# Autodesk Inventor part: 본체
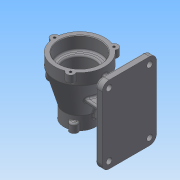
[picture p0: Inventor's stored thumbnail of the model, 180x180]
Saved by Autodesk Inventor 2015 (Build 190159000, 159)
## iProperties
Created: 2020-03
Part Number: 본체
Material: 일반
Document SubType Name: Modeling
Designer: user
Density: 1 g/cm^3
Appearance: 기본값
Author: user
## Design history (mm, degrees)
sketch "스케치1"
  geometry: L1 (0, 0)-(0, 100); L2 (0, 100)-(44, 100); L3 (0, 0)-(27.5, 0); L4 (27.5, 0)-(27.5, 23); L5 (44, 100)-(44, 80); L6 (44, 80)-(27.5, 23)
  constraints: 12 end point, 2 horizontal, 2 vertical, 1 perpendicular
  dimensions: "d0" = 100 distance of L1.start L1.end; "d1" = 44 distance of L1.end L2.end; "d3" = 27.5 distance of L1.start L3.end; "d4" = 23 distance of L3.end L4.end; "d5" = 20 distance of L2.end L5.end
revolve "회전1" sketch "스케치1" stored, may be unused: angle "d6" = 90 deg
hole "구멍1" diameter "d9" = 72; stored, may be unused: countersink angle "d13" = 90 deg, drill point angle "d15" = 0 deg; dims "d7" = 10, "d8" = 10, "d10" = 6, "d11" = 4, "d12" = 2, "d14" = 23
hole "구멍2" diameter "d18" = 52; stored, may be unused: countersink angle "d22" = 90 deg, drill point angle "d24" = 0 deg; dims "d16" = 10, "d17" = 10, "d19" = 6, "d20" = 4, "d21" = 2, "d23" = 47
hole "구멍3" diameter "d27" = 40; stored, may be unused: countersink angle "d31" = 90 deg, drill point angle "d33" = 0 deg; dims "d25" = 10, "d26" = 10, "d28" = 6, "d29" = 4, "d30" = 2, "d32" = 30
chamfer "모따기1" distance "d34" = 1; stored, may be unused: second distance "d35" = 2, angle "d36" = 45 deg
chamfer "모따기2" distance "d37" = 1; stored, may be unused: second distance "d38" = 2, angle "d39" = 45 deg
fillet "모깎기1" dims "d40" = 3
node "작업 평면1"
sketch "스케치2"
  geometry: L1 (-47.5, -16)-(-47.5, 119); L2 (47.5, -16)-(47.5, 119); L3 (-27.5, 23)-(27.5, 23) reference; L4 (-44, 80)-(44, 80) reference; L5 (-44, 80)-(-27.5, 23) reference; L6 (44, 80)-(27.5, 23) reference; L7 (-44, 80)-(44, 80) reference; L8 (-44, 100)-(44, 100) reference; L9 (-27.5, 0)-(27.5, 0) reference; L10 (-27.5, 0)-(27.5, 0) reference; L11 (-27.5, 23)-(27.5, 23) reference; L12 (-35.75, 51.5)-(-47.5, 51.5); L13 (47.5, 119)-(-47.5, 119); L14 (47.5, -16)-(-47.5, -16); 1 further point
  constraints: 10 end point, 3 parallel, 2 midpoint, 1 perpendicular
  dimensions: "d43" = 95 distance between parallel lines of L1 L2; "d44" = 67.5 distance between parallel lines of L12 L13; "d45" = 67.5 distance between parallel lines of L12 L14
extrude "돌출1" join sketch "스케치2" distance "d46" = 12; taper "d47" = 0 deg
fillet "모깎기2" dims "d48" = 12
fillet "모깎기3" dims "d49" = 3
sketch "스케치3"
  geometry: L1 (51.5, 4)-(51.5, -4); L2 (14.5, 4)-(14.5, -4); L3 (88.5, 4)-(88.5, -4); L4 (14.5, 0)-(88.5, 0); L5 (14.5, 4)-(88.5, 4); L6 (14.5, -4)-(88.5, -4); 1 further point
  constraints: 12 end point, 4 midpoint, 4 parallel
  dimensions: "d50" = 37 distance between parallel lines of L1 L2; "d51" = 37 distance between parallel lines of L1 L3; "d52" = 4 distance between parallel lines of L4 L5; "d53" = 4 distance between parallel lines of L4 L6
extrude "돌출2" join sketch "스케치3" stored distance "d54" = 12; taper "d55" = 0 deg
node "작업 평면2"
sketch "스케치4"
  geometry: L1 (0, 39.5)-(0, -31.5) reference; L2 (0, 8)-(31.182, 8) reference; L3 (0, 0)-(31.182, 0) reference; L4 (0, 29)-(50.148, 24.613); L5 (0, -21)-(50.148, -16.613); L6 (31.182, 8)-(47.792, 8) reference; L7 (47.792, 0)-(31.182, 0) reference; L8 (39.223, 8)-(0, 8); L9 (39.223, 0)-(0, 0); C1 r 36 at (75, 4) reference; A1 r 44 centre (75, 4) between (31.182, 0) and (31.182, 8) reference; A2 r 32.288 centre (75, 4) between (50.148, 24.613) and (50.148, -16.613); 3 further points
  constraints: 8 end point, 4 point on line, 2 point on circle, 1 centre point, 1 coincident, 1 collinear, 1 horizontal
  dimensions: "d58" = 95 deg angle of L1 L4
extrude "돌출4" join sketch "스케치4" stored distance "d63" = 8; taper "d64" = 0 deg
fillet "모깎기4" dims "d65" = 3
fillet "모깎기5" dims "d66" = 3
sketch "스케치5"
  geometry: C1 r 5 at (107, -35.5); C2 r 5 at (107, 35.5); C3 r 5 at (-4, 35.5); C4 r 5 at (-4, -35.5); A1 r 9 centre (107, -35.5) between (107, -44.5) and (116, -35.5) reference; A2 r 9 centre (107, 35.5) between (116, 35.5) and (107, 44.5) reference; A3 r 9 centre (-4, 35.5) between (-4, 44.5) and (-13, 35.5) reference; A4 r 9 centre (-4, -35.5) between (-13, -35.5) and (-4, -44.5) reference; 1 further point
  constraints: 4 centre point, 4 coincident
  dimensions: "d67" = 10 diameter of C1; "d68" = 10 diameter of C2; "d69" = 10 diameter of C3; "d70" = 10 diameter of C4
extrude "돌출5" cut sketch "스케치5" distance "d71" = 12; taper "d72" = 0 deg
node "작업 평면3"
sketch "스케치7"
  geometry: L1 (0, 0)-(-62.801, 0); C1 r 37 at (0, 0) reference; C2 r 7 at (-44, 0); C3 r 7 at (22, -38.105); C4 r 7 at (22, 38.105); 1 further point
  constraints: 3 centre point, 2 end point, 1 horizontal, 1 horizontal alignment, 1 point on line, 8 other
  dimensions: "d89" = 14 diameter of C2; "d92" = 360 deg dimension on point (0, 0) C2.centre (derived)
extrude "돌출7" join sketch "스케치7" distance "d94" = 15; taper "d95" = 0 deg
fillet "모깎기6" dims "d96" = 3
fillet "모깎기7" dims "d97" = 3
fillet "모깎기8" dims "d98" = 1
sketch "스케치8"
  geometry: C1 r 1.474 at (0, 0); A1 r 7 centre (0, 0) between (-0.249, 6.996) and (-0.249, -6.996) reference
  constraints: 1 centre point, 1 coincident
hole "구멍5" sketch "스케치8" at (0, 0) diameter "d99" = 4.134; stored, may be unused: countersink angle "d103" = 90 deg, drill point angle "d105" = 118 deg; dims "d100" = 9, "d101" = 4, "d102" = 2, "d104" = 11
sketch "스케치9"
  geometry: L1 (0, 0)-(37.161, 0); C1 r 21 at (0, 0) reference; A1 r 27.5 centre (0, 0) between (27.5, 0) and (26.609, -6.943) reference; A2 r 7 centre (27.5, 0) between (26.609, -6.943) and (26.609, 6.943); A3 r 27.5 centre (0, 0) between (26.609, -6.943) and (26.609, 6.943)
  constraints: 8 point on circle, 2 centre point, 2 end point, 1 coincident, 1 horizontal, 1 point on line
  dimensions: "d109" = 14 diameter of A2
extrude "돌출8" join sketch "스케치9" distance "d110" = 15; taper "d111" = 0 deg
fillet "모깎기9" dims "d115" = 3
fillet "모깎기10" dims "d116" = 1
sketch "스케치10"
  geometry: C1 r 1.816 at (0, 0); A1 r 7 centre (0, 0) between (-0.127, 6.999) and (-0.127, -6.999) reference
  constraints: 1 centre point, 1 coincident
hole "구멍6" sketch "스케치10" at (0, 0) diameter "d117" = 4.134; stored, may be unused: countersink angle "d121" = 90 deg, drill point angle "d123" = 118 deg; dims "d118" = 9, "d119" = 4, "d120" = 2, "d122" = 11
sketch "스케치11"
  geometry: L1 (52.5, 27.749)-(50.5, 27.749) reference; L2 (107, 47.5)-(-4, 47.5) reference; L3 (51.5, 27.749)-(51.5, 57.771); L4 (107, 37.5)-(-4, 37.5); 3 further points
  constraints: 4 end point, 2 midpoint, 1 coincident, 1 parallel, 1 vertical, 1 other
  dimensions: "d127" = 10 distance between parallel lines of L2 L4
feature "엠보싱1" sketch "스케치11" dims "d0" = 100, "d1" = 44, "d3" = 27.5, "d4" = 23, "d5" = 20, "d128" = 0.5, "d129" = 0
sketch "스케치12"
  geometry: L1 (-100, 7.817)-(-100, 44) reference; L2 (-100, -44)-(-100, -7.817) reference; L3 (-100, -6.996)-(-100, 6.996) reference; L4 (-50, -44)-(-50, 0); L5 (0, 0)-(-71.716, 0); C1 r 15 at (-50, 0); 2 further points
  constraints: 4 end point, 1 centre point, 1 coincident, 1 horizontal, 1 parallel, 1 point on line
  dimensions: "d132" = 50 distance between parallel lines of L2 L4; "d133" = 30 diameter of C1
extrude "돌출9" join sketch "스케치12" stored distance "d134" = 15; taper "d135" = 0 deg
hole "구멍7" diameter "d138" = 20; stored, may be unused: countersink angle "d142" = 90 deg, drill point angle "d144" = 0 deg; dims "d136" = 10, "d137" = 10, "d139" = 10, "d140" = 4, "d141" = 2, "d143" = 30
chamfer "모따기4" distance "d145" = 1; stored, may be unused: second distance "d146" = 2, angle "d147" = 45 deg
fillet "모깎기11" dims "d148" = 1
node "솔리드1"
pattern_circular "원형 패턴1" dims angle "d107" = 360 deg
pattern_circular "원형 패턴2" dims angle "d113" = 360 deg
pattern_circular "원형 패턴3" dims angle "d125" = 360 deg
node "투영된 루프1"
node "투영된 루프2"
node "투영된 루프3"
other parameters: "d41" = 87, "d62" = 8, "d73" = -132
